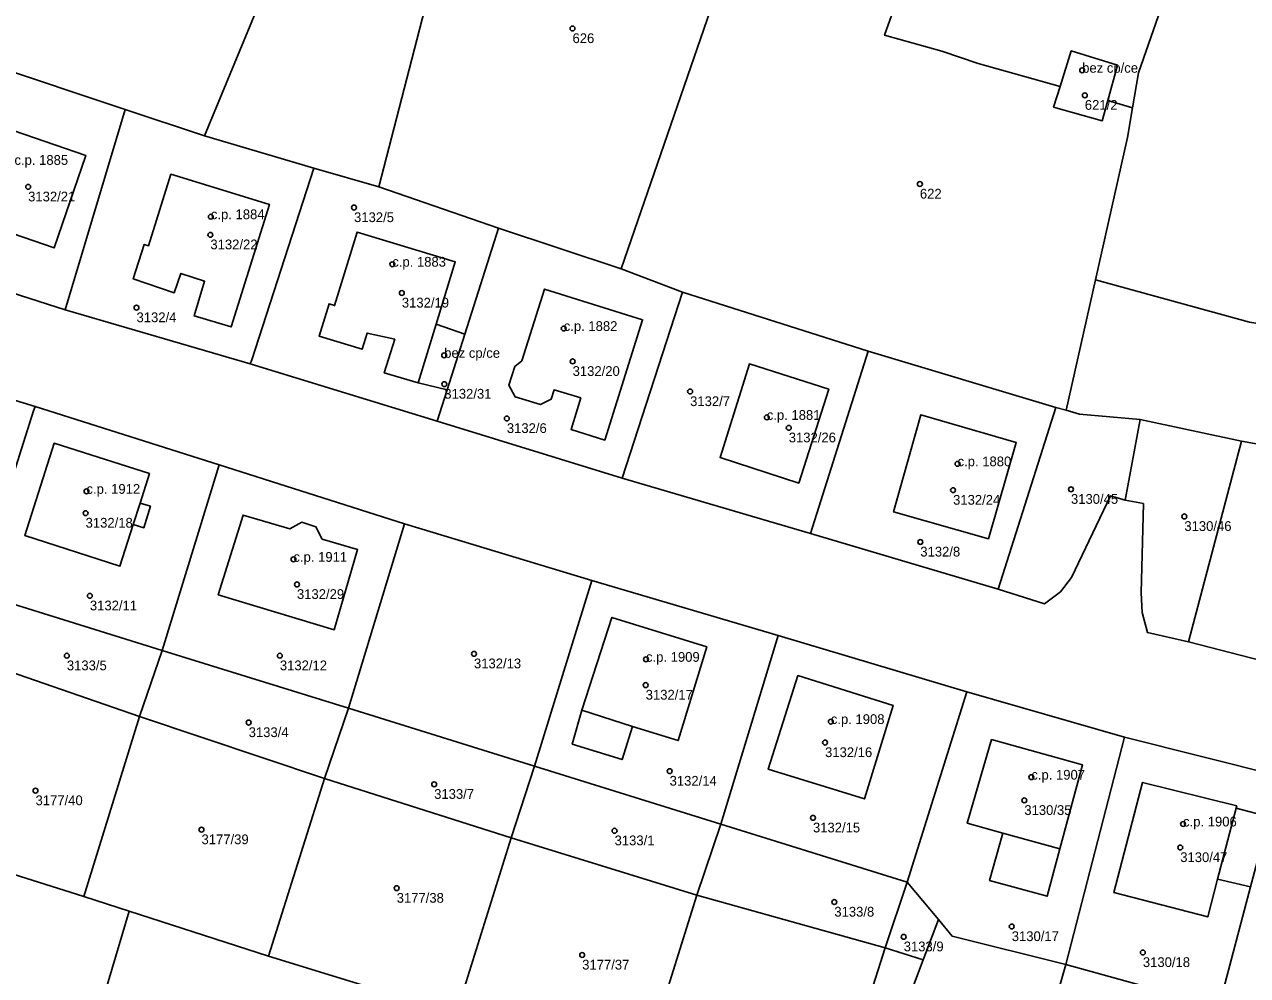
# Model space of a CAD drawing. Extents: x -878211 to -870363, y -1058464 to -1052522.
# Drawn here: x -874523.6 to -874398.3, y -1056692 to -1056594.5 of the extents above; entities that cross this region are included whole.
import ezdxf

# ---------------------------------------------------------------- set-up
doc = ezdxf.new("R2010")
doc.units = 0
for name, color, linetype in [('Vrstva 50', 7, 'Continuous'), ('Vrstva 51', 7, 'Continuous'), ('Vrstva 52', 7, 'Continuous')]:
    doc.layers.add(name, color=color, linetype=linetype)

msp = doc.modelspace()

# ---------------------------------------------------------------- linework, layer by layer
at = {"layer": 'Vrstva 50'}
for centre in [(-874467.44, -1056594.87994), (-874415.21, -1056599.15994), (-874414.94, -1056601.71994), (-874523.23, -1056611.10994), (-874431.84, -1056610.81994), (-874504.5, -1056614.16994), (-874489.83, -1056613.22994), (-874504.55, -1056616.01994), (-874485.91, -1056619.03994), (-874484.93, -1056621.98994), (-874512.12, -1056623.48994), (-874468.34, -1056625.62994), (-874480.59, -1056628.37994), (-874467.43, -1056628.99994), (-874480.58, -1056631.32994), (-874455.39, -1056632.08994), (-874474.17, -1056634.84994), (-874447.53, -1056634.73994), (-874445.28, -1056635.80994), (-874427.98, -1056639.49994), (-874517.25, -1056642.31994), (-874428.44, -1056642.19994), (-874416.36, -1056642.10994), (-874517.34, -1056644.54994), (-874404.74, -1056644.88994), (-874431.8, -1056647.50994), (-874496.04, -1056649.28994), (-874495.68, -1056651.85994), (-874516.9, -1056653.02994), (-874519.26, -1056659.16994), (-874497.43, -1056659.16994), (-874477.54, -1056658.96994), (-874459.91, -1056659.53994), (-874459.94, -1056662.17994), (-874500.63, -1056666.01994), (-874440.97, -1056665.91994), (-874441.56, -1056668.06994), (-874457.49, -1056670.99994), (-874420.42, -1056671.61994), (-874522.47, -1056672.99994), (-874481.62, -1056672.34994), (-874421.14, -1056673.99994), (-874505.46, -1056676.99994), (-874442.8, -1056675.78994), (-874404.87, -1056676.41994), (-874463.13, -1056677.10994), (-874405.16, -1056678.82994), (-874485.46, -1056682.99994), (-874440.61, -1056684.41994), (-874422.43, -1056686.92994), (-874433.5, -1056687.97994), (-874466.45, -1056689.84994), (-874408.99, -1056689.58994)]:
    msp.add_circle(centre, 0.25, dxfattribs=at)
at = {"layer": 'Vrstva 51'}
for points in [[(-874482.68, -1056552), (-874492.23, -1056574.63), (-874505.17, -1056605.89), (-874493.95, -1056609.2), (-874487.28, -1056611.12), (-874472.96, -1056555.68), (-874476.32, -1056554.41), (-874477.4, -1056553.99)], [(-874472.96, -1056555.68), (-874487.28, -1056611.12), (-874475.03, -1056615.34), (-874462.44, -1056619.5), (-874452.28, -1056589.96), (-874459.59, -1056587.43), (-874457.06, -1056577.35), (-874452.98, -1056562.31), (-874459.26, -1056559.96), (-874463.6, -1056558.33), (-874472.65, -1056554.94)], [(-874492.23, -1056574.63), (-874501.67, -1056571.24), (-874510.67, -1056567.24), (-874515.54, -1056565.34), (-874527.34, -1056598.5), (-874513.29, -1056603.18), (-874505.17, -1056605.89)], [(-874399.15, -1056580.65), (-874413.96, -1056575.21), (-874417.44, -1056579.26), (-874424.45, -1056585.79), (-874431.52, -1056583.55), (-874433.84, -1056591.24), (-874434.41, -1056592.58), (-874435.46, -1056595.57), (-874429.59, -1056597.21), (-874425.86, -1056598.45), (-874417.47, -1056600.82), (-874416.33, -1056597.18), (-874411.58, -1056598.63), (-874412.58, -1056602.26), (-874410.04, -1056603), (-874409.44, -1056599.43), (-874406.65, -1056591.37)], [(-874425.86, -1056598.45), (-874429.59, -1056597.21), (-874435.46, -1056595.57), (-874434.41, -1056592.58), (-874433.84, -1056591.24), (-874431.52, -1056583.55), (-874448.75, -1056579.37), (-874457.06, -1056577.35), (-874459.59, -1056587.43), (-874452.28, -1056589.96), (-874462.44, -1056619.5), (-874456.17, -1056621.91), (-874437.15, -1056627.95), (-874417.92, -1056633.73), (-874416.85, -1056634), (-874413.84, -1056620.64), (-874410.55, -1056606.05), (-874410.04, -1056603), (-874412.58, -1056602.26), (-874413.16, -1056604.33), (-874418.14, -1056602.93), (-874417.47, -1056600.82)], [(-874390.92, -1056582.93), (-874399.15, -1056580.65), (-874406.65, -1056591.37), (-874409.44, -1056599.43), (-874410.04, -1056603), (-874410.55, -1056606.05), (-874413.84, -1056620.64), (-874398.08, -1056624.97), (-874371.71, -1056629.09), (-874371.71, -1056611.62), (-874372.19, -1056611.57), (-874375.58, -1056611.24), (-874381.94, -1056609.81), (-874392.72, -1056607.44), (-874392.18, -1056604.62), (-874390.79, -1056601.51)], [(-874519.44, -1056623.7), (-874513.29, -1056603.18), (-874527.34, -1056598.5), (-874531.91, -1056597.08), (-874538.75, -1056617.53)], [(-874413.16, -1056604.33), (-874412.58, -1056602.26), (-874411.58, -1056598.63), (-874416.33, -1056597.18), (-874417.47, -1056600.82), (-874418.14, -1056602.93)], [(-874500.32, -1056628.85), (-874493.95, -1056609.2), (-874505.17, -1056605.89), (-874513.29, -1056603.18), (-874519.44, -1056623.7), (-874500.47, -1056629.25)], [(-874526.88, -1056604.61), (-874530.12, -1056614.09), (-874520.57, -1056617.36), (-874517.32, -1056607.88)], [(-874526.88, -1056604.61), (-874517.32, -1056607.88), (-874520.57, -1056617.36), (-874530.12, -1056614.09)], [(-874510.89, -1056617.14), (-874511.33, -1056617), (-874512.45, -1056620.54), (-874508.25, -1056621.96), (-874507.58, -1056619.98), (-874505.15, -1056620.78), (-874506.21, -1056624.33), (-874502.43, -1056625.46), (-874498.5, -1056612.91), (-874508.59, -1056609.82)], [(-874510.89, -1056617.14), (-874508.59, -1056609.82), (-874498.5, -1056612.91), (-874502.43, -1056625.46), (-874506.21, -1056624.33), (-874505.15, -1056620.78), (-874507.58, -1056619.98), (-874508.25, -1056621.96), (-874512.45, -1056620.54), (-874511.33, -1056617)], [(-874489.51, -1056615.75), (-874479.46, -1056618.78), (-874481.42, -1056625.19), (-874478.49, -1056626.21), (-874475.03, -1056615.34), (-874487.28, -1056611.12), (-874493.95, -1056609.2), (-874500.32, -1056628.85), (-874500.47, -1056629.25), (-874481.31, -1056635.12), (-874480.3, -1056631.93), (-874483.25, -1056631.18), (-874486.73, -1056630.16), (-874485.66, -1056626.72), (-874488.48, -1056626.09), (-874489, -1056627.76), (-874493.41, -1056626.4), (-874492.38, -1056623.09), (-874491.82, -1056623.27)], [(-874456.17, -1056621.91), (-874462.44, -1056619.5), (-874475.03, -1056615.34), (-874478.49, -1056626.21), (-874480.3, -1056631.93), (-874481.31, -1056635.12), (-874462.35, -1056640.98)], [(-874483.25, -1056631.18), (-874481.42, -1056625.19), (-874479.46, -1056618.78), (-874489.51, -1056615.75), (-874491.82, -1056623.27), (-874492.38, -1056623.09), (-874493.41, -1056626.4), (-874489, -1056627.76), (-874488.48, -1056626.09), (-874485.66, -1056626.72), (-874486.73, -1056630.16)], [(-874464.13, -1056637.06), (-874467.58, -1056635.97), (-874466.6, -1056632.74), (-874469.33, -1056631.92), (-874469.63, -1056632.87), (-874470.71, -1056633.4), (-874473.32, -1056632.62), (-874473.96, -1056631.43), (-874473.36, -1056629.52), (-874472.65, -1056628.94), (-874470.3, -1056621.59), (-874460.26, -1056624.73)], [(-874464.13, -1056637.06), (-874460.26, -1056624.73), (-874470.3, -1056621.59), (-874472.65, -1056628.94), (-874473.36, -1056629.52), (-874473.96, -1056631.43), (-874473.32, -1056632.62), (-874470.71, -1056633.4), (-874469.63, -1056632.87), (-874469.33, -1056631.92), (-874466.6, -1056632.74), (-874467.58, -1056635.97)], [(-874415.48, -1056634.41), (-874409.26, -1056634.97), (-874398.9, -1056637.18), (-874380.41, -1056640.49), (-874372.85, -1056641.69), (-874371.71, -1056629.09), (-874398.08, -1056624.97), (-874413.84, -1056620.64), (-874416.85, -1056634)], [(-874437.15, -1056627.95), (-874456.17, -1056621.91), (-874462.35, -1056640.98), (-874443.06, -1056646.64)], [(-874478.49, -1056626.21), (-874481.42, -1056625.19), (-874483.25, -1056631.18), (-874480.3, -1056631.93)], [(-874547.67, -1056646.74), (-874528.58, -1056652.68), (-874522.69, -1056634.07), (-874522.52, -1056633.61), (-874542.01, -1056627.68)], [(-874417.92, -1056633.73), (-874437.15, -1056627.95), (-874443.06, -1056646.64), (-874423.82, -1056652.34)], [(-874449.31, -1056629.26), (-874441.18, -1056631.86), (-874444.26, -1056641.48), (-874452.32, -1056638.84)], [(-874449.31, -1056629.26), (-874452.32, -1056638.84), (-874444.26, -1056641.48), (-874441.18, -1056631.86)], [(-874509.49, -1056658.62), (-874503.66, -1056639.59), (-874522.52, -1056633.61), (-874522.69, -1056634.07), (-874528.58, -1056652.68)], [(-874410.8, -1056643.23), (-874409.26, -1056634.97), (-874415.48, -1056634.41), (-874416.85, -1056634), (-874417.92, -1056633.73), (-874423.82, -1056652.34), (-874419.07, -1056653.84), (-874417.43, -1056652.61), (-874416.29, -1056651.16), (-874412.32, -1056642.79)], [(-874421.96, -1056637.32), (-874424.82, -1056647.18), (-874434.54, -1056644.43), (-874431.73, -1056634.46)], [(-874421.96, -1056637.32), (-874431.73, -1056634.46), (-874434.54, -1056644.43), (-874424.82, -1056647.18)], [(-874410.8, -1056643.23), (-874408.93, -1056643.57), (-874409.16, -1056652.73), (-874409.07, -1056654.73), (-874408.53, -1056656.8), (-874404.31, -1056657.76), (-874398.9, -1056637.18), (-874409.26, -1056634.97)], [(-874523.57, -1056646.83), (-874520.55, -1056637.39), (-874510.8, -1056640.5), (-874511.76, -1056643.53), (-874510.69, -1056643.85), (-874511.38, -1056646.05), (-874512.46, -1056645.71), (-874513.82, -1056650)], [(-874523.57, -1056646.83), (-874513.82, -1056650), (-874512.46, -1056645.71), (-874511.38, -1056646.05), (-874510.69, -1056643.85), (-874511.76, -1056643.53), (-874510.8, -1056640.5), (-874520.55, -1056637.39)], [(-874380.41, -1056640.49), (-874398.9, -1056637.18), (-874404.31, -1056657.76), (-874385.91, -1056662.51)], [(-874490.41, -1056664.56), (-874484.66, -1056645.64), (-874503.66, -1056639.59), (-874509.49, -1056658.62)], [(-874493.73, -1056645.94), (-874493.08, -1056647.22), (-874489.47, -1056648.28), (-874491.88, -1056656.51), (-874503.74, -1056652.91), (-874501.2, -1056644.75), (-874496.42, -1056646.15), (-874495.18, -1056645.48)], [(-874493.73, -1056645.94), (-874495.18, -1056645.48), (-874496.42, -1056646.15), (-874501.2, -1056644.75), (-874503.74, -1056652.91), (-874491.88, -1056656.51), (-874489.47, -1056648.28), (-874493.08, -1056647.22)], [(-874465.47, -1056651.46), (-874484.66, -1056645.64), (-874490.41, -1056664.56), (-874471.32, -1056670.5)], [(-874446.38, -1056657.11), (-874465.47, -1056651.46), (-874471.32, -1056670.5), (-874452.23, -1056676.43)], [(-874528.58, -1056652.68), (-874530.51, -1056658.93), (-874511.82, -1056665.4), (-874509.49, -1056658.62)], [(-874453.68, -1056658.26), (-874463.4, -1056655.24), (-874466.47, -1056664.75), (-874467.46, -1056668.23), (-874462.36, -1056669.82), (-874461.3, -1056666.41), (-874456.6, -1056667.86)], [(-874453.68, -1056658.26), (-874456.6, -1056667.86), (-874461.3, -1056666.41), (-874462.36, -1056669.82), (-874467.46, -1056668.23), (-874466.47, -1056664.75), (-874463.4, -1056655.24)], [(-874427.04, -1056662.88), (-874446.38, -1056657.11), (-874452.23, -1056676.43), (-874433.14, -1056682.38)], [(-874536.59, -1056677.84), (-874517.53, -1056683.84), (-874511.82, -1056665.4), (-874530.51, -1056658.93)], [(-874509.49, -1056658.62), (-874511.82, -1056665.4), (-874492.86, -1056671.77), (-874490.41, -1056664.56)], [(-874437.51, -1056673.84), (-874434.59, -1056664.26), (-874444.34, -1056661.21), (-874447.38, -1056670.81)], [(-874437.51, -1056673.84), (-874447.38, -1056670.81), (-874444.34, -1056661.21), (-874434.59, -1056664.26)], [(-874427.04, -1056662.88), (-874433.14, -1056682.38), (-874429.95, -1056686.22), (-874428.55, -1056687.91), (-874416.89, -1056690.83), (-874410.86, -1056667.5)], [(-874512.89, -1056685.34), (-874498.58, -1056689.97), (-874492.86, -1056671.77), (-874511.82, -1056665.4), (-874517.53, -1056683.84)], [(-874473.72, -1056677.82), (-874471.32, -1056670.5), (-874490.41, -1056664.56), (-874492.86, -1056671.77)], [(-874417.51, -1056678.97), (-874418.8, -1056683.83), (-874424.7, -1056682.21), (-874423.34, -1056677.37), (-874426.99, -1056676.34), (-874424.49, -1056667.76), (-874415.17, -1056670.35)], [(-874417.51, -1056678.97), (-874415.17, -1056670.35), (-874424.49, -1056667.76), (-874426.99, -1056676.34), (-874423.34, -1056677.37), (-874424.7, -1056682.21), (-874418.8, -1056683.83)], [(-874409.02, -1056672.15), (-874399.37, -1056674.57), (-874399.42, -1056674.81), (-874396.04, -1056675.67), (-874394.94, -1056671.52), (-874410.86, -1056667.5), (-874416.89, -1056690.83), (-874401.22, -1056695.15), (-874397.95, -1056682.85), (-874401.33, -1056682.07), (-874402.34, -1056685.95), (-874411.97, -1056683.44)], [(-874471.32, -1056670.5), (-874473.72, -1056677.82), (-874454.69, -1056683.71), (-874452.23, -1056676.43)], [(-874396.04, -1056675.67), (-874397.95, -1056682.85), (-874401.22, -1056695.15), (-874385.04, -1056699.32), (-874378.88, -1056675.53), (-874394.94, -1056671.52)], [(-874479.36, -1056695.89), (-874473.72, -1056677.82), (-874492.86, -1056671.77), (-874498.58, -1056689.97)], [(-874396.04, -1056675.67), (-874399.42, -1056674.81), (-874399.37, -1056674.57), (-874409.02, -1056672.15), (-874411.97, -1056683.44), (-874402.34, -1056685.95), (-874401.33, -1056682.07), (-874397.95, -1056682.85)], [(-874520.36, -1056710.57), (-874519.51, -1056707.69), (-874514.47, -1056705.1), (-874517.18, -1056699.85), (-874512.89, -1056685.34), (-874517.53, -1056683.84), (-874536.59, -1056677.84), (-874541.03, -1056676.46), (-874548.64, -1056702.2)], [(-874433.14, -1056682.38), (-874452.23, -1056676.43), (-874454.69, -1056683.71), (-874435.39, -1056689.11)], [(-874473.72, -1056677.82), (-874479.36, -1056695.89), (-874460.36, -1056701.86), (-874454.69, -1056683.71)], [(-874435.39, -1056689.11), (-874431.5, -1056690.35), (-874429.95, -1056686.22), (-874433.14, -1056682.38)], [(-874454.69, -1056683.71), (-874460.36, -1056701.86), (-874441.33, -1056707.79), (-874438.87, -1056700.06), (-874435.39, -1056689.11)], [(-874512.89, -1056685.34), (-874517.18, -1056699.85), (-874514.47, -1056705.1), (-874511.88, -1056710.13), (-874494.62, -1056715.24), (-874486.23, -1056717.71), (-874482.63, -1056706.27), (-874479.36, -1056695.89), (-874498.58, -1056689.97)], [(-874429.95, -1056686.22), (-874431.5, -1056690.35), (-874435.46, -1056700.9), (-874420.78, -1056704.5), (-874416.89, -1056690.83), (-874428.55, -1056687.91)], [(-874438.87, -1056700.06), (-874441.33, -1056707.79), (-874438.03, -1056708.82), (-874435.46, -1056700.9), (-874431.5, -1056690.35), (-874435.39, -1056689.11)], [(-874404.63, -1056708.63), (-874401.71, -1056697.09), (-874401.22, -1056695.15), (-874416.89, -1056690.83), (-874420.78, -1056704.5)]]:
    msp.add_lwpolyline(points, close=True, dxfattribs=at)
for points in [[(-874674.5, -1056611.53), (-874654.24, -1056611.37), (-874630.82, -1056611.95), (-874607.22, -1056614.22), (-874583.78, -1056617.4), (-874585.46, -1056627.16), (-874580.67, -1056628.5), (-874576.97, -1056624.18), (-874577.84, -1056628.61), (-874576.13, -1056629.76), (-874573.21, -1056619.53), (-874560.17, -1056622.07), (-874542.01, -1056627.68), (-874522.52, -1056633.61), (-874503.66, -1056639.59), (-874484.66, -1056645.64), (-874465.47, -1056651.46), (-874446.38, -1056657.11), (-874427.04, -1056662.88), (-874410.86, -1056667.5), (-874394.94, -1056671.52)], [(-874385.91, -1056662.51), (-874404.31, -1056657.76), (-874408.53, -1056656.8), (-874409.07, -1056654.73), (-874409.16, -1056652.73), (-874408.93, -1056643.57), (-874410.8, -1056643.23), (-874412.32, -1056642.79), (-874416.29, -1056651.16), (-874417.43, -1056652.61), (-874419.07, -1056653.84), (-874423.82, -1056652.34), (-874443.06, -1056646.64), (-874462.35, -1056640.98), (-874481.31, -1056635.12), (-874500.47, -1056629.25), (-874519.44, -1056623.7), (-874538.75, -1056617.53)]]:
    msp.add_lwpolyline(points, dxfattribs=at)
at = {"layer": 'Vrstva 52'}
for points in [[(-874417.47, -1056600.82), (-874418.14, -1056602.93), (-874413.16, -1056604.33), (-874412.58, -1056602.26), (-874411.58, -1056598.63), (-874416.33, -1056597.18)], [(-874530.12, -1056614.09), (-874520.57, -1056617.36), (-874517.32, -1056607.88), (-874526.88, -1056604.61)], [(-874508.25, -1056621.96), (-874507.58, -1056619.98), (-874505.15, -1056620.78), (-874506.21, -1056624.33), (-874502.43, -1056625.46), (-874498.5, -1056612.91), (-874508.59, -1056609.82), (-874510.89, -1056617.14), (-874511.33, -1056617), (-874512.45, -1056620.54)], [(-874493.41, -1056626.4), (-874489, -1056627.76), (-874488.48, -1056626.09), (-874485.66, -1056626.72), (-874486.73, -1056630.16), (-874483.25, -1056631.18), (-874481.42, -1056625.19), (-874479.46, -1056618.78), (-874489.51, -1056615.75), (-874491.82, -1056623.27), (-874492.38, -1056623.09)], [(-874473.36, -1056629.52), (-874473.96, -1056631.43), (-874473.32, -1056632.62), (-874470.71, -1056633.4), (-874469.63, -1056632.87), (-874469.33, -1056631.92), (-874466.6, -1056632.74), (-874467.58, -1056635.97), (-874464.13, -1056637.06), (-874460.26, -1056624.73), (-874470.3, -1056621.59), (-874472.65, -1056628.94)], [(-874480.3, -1056631.93), (-874478.49, -1056626.21), (-874481.42, -1056625.19), (-874483.25, -1056631.18)], [(-874452.32, -1056638.84), (-874444.26, -1056641.48), (-874441.18, -1056631.86), (-874449.31, -1056629.26)], [(-874434.54, -1056644.43), (-874424.82, -1056647.18), (-874421.96, -1056637.32), (-874431.73, -1056634.46)], [(-874512.46, -1056645.71), (-874511.76, -1056643.53), (-874510.8, -1056640.5), (-874520.55, -1056637.39), (-874523.57, -1056646.83), (-874513.82, -1056650)], [(-874503.74, -1056652.91), (-874491.88, -1056656.51), (-874489.47, -1056648.28), (-874493.08, -1056647.22), (-874493.73, -1056645.94), (-874495.18, -1056645.48), (-874496.42, -1056646.15), (-874501.2, -1056644.75)], [(-874466.47, -1056664.75), (-874461.3, -1056666.41), (-874456.6, -1056667.86), (-874453.68, -1056658.26), (-874463.4, -1056655.24)], [(-874447.38, -1056670.81), (-874437.51, -1056673.84), (-874434.59, -1056664.26), (-874444.34, -1056661.21)], [(-874426.99, -1056676.34), (-874423.34, -1056677.37), (-874417.51, -1056678.97), (-874415.17, -1056670.35), (-874424.49, -1056667.76)], [(-874399.37, -1056674.57), (-874409.02, -1056672.15), (-874411.97, -1056683.44), (-874402.34, -1056685.95), (-874401.33, -1056682.07), (-874399.42, -1056674.81)]]:
    msp.add_lwpolyline(points, close=True, dxfattribs=at)

# ---------------------------------------------------------------- texts
at = {"layer": 'Vrstva 50'}
for s, p in [('626', (-874467.44, -1056596.369)), ('bez cp/ce', (-874415.21, -1056599.409)), ('621/2', (-874414.94, -1056603.209)), ('c.p. 1885', (-874524.63, -1056608.85)), ('3132/21', (-874523.23, -1056612.599)), ('622', (-874431.84, -1056612.309)), ('c.p. 1884', (-874504.5, -1056614.419)), ('3132/5', (-874489.83, -1056614.719)), ('3132/22', (-874504.55, -1056617.509)), ('c.p. 1883', (-874485.91, -1056619.29)), ('3132/19', (-874484.93, -1056623.479)), ('3132/4', (-874512.12, -1056624.979)), ('c.p. 1882', (-874468.34, -1056625.879)), ('bez cp/ce', (-874480.59, -1056628.629)), ('3132/20', (-874467.43, -1056630.489)), ('3132/31', (-874480.58, -1056632.819)), ('3132/7', (-874455.39, -1056633.579)), ('c.p. 1881', (-874447.53, -1056634.99)), ('3132/6', (-874474.17, -1056636.339)), ('3132/26', (-874445.28, -1056637.299)), ('c.p. 1880', (-874427.98, -1056639.75)), ('c.p. 1912', (-874517.25, -1056642.57)), ('3132/24', (-874428.44, -1056643.689)), ('3130/45', (-874416.36, -1056643.599)), ('3132/18', (-874517.34, -1056646.039)), ('3130/46', (-874404.74, -1056646.379)), ('c.p. 1911', (-874496.04, -1056649.54)), ('3132/8', (-874431.8, -1056648.999)), ('3132/29', (-874495.68, -1056653.349)), ('3132/11', (-874516.9, -1056654.519)), ('c.p. 1909', (-874459.91, -1056659.79)), ('3133/5', (-874519.26, -1056660.659)), ('3132/12', (-874497.43, -1056660.659)), ('3132/13', (-874477.54, -1056660.459)), ('3132/17', (-874459.94, -1056663.669)), ('c.p. 1908', (-874440.97, -1056666.169)), ('3133/4', (-874500.63, -1056667.509)), ('3132/16', (-874441.56, -1056669.559)), ('3132/14', (-874457.49, -1056672.489)), ('c.p. 1907', (-874420.42, -1056671.87)), ('3133/7', (-874481.62, -1056673.839)), ('3177/40', (-874522.47, -1056674.489)), ('3130/35', (-874421.14, -1056675.489)), ('3132/15', (-874442.8, -1056677.279)), ('c.p. 1906', (-874404.87, -1056676.669)), ('3177/39', (-874505.46, -1056678.489)), ('3133/1', (-874463.13, -1056678.599)), ('3130/47', (-874405.16, -1056680.319)), ('3177/38', (-874485.46, -1056684.489)), ('3133/8', (-874440.61, -1056685.909)), ('3130/17', (-874422.43, -1056688.419)), ('3133/9', (-874433.5, -1056689.469)), ('3177/37', (-874466.45, -1056691.339)), ('3130/18', (-874408.99, -1056691.079))]:
    msp.add_text(s, height=0.999996, dxfattribs=at).set_placement(p)

doc.saveas('drawing.dxf')
